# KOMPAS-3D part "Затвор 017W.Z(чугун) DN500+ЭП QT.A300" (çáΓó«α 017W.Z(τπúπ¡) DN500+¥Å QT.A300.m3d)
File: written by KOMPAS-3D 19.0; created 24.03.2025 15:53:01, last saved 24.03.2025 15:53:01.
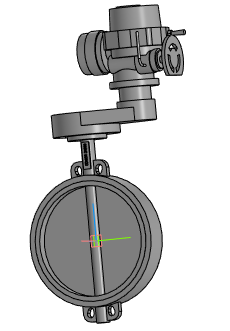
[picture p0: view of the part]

Document properties: Полное имя файла: Затвор 017W.Z(чугун) DN500+ЭП QT.A300.a3d

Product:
- Part/product: Затвор 017W.Z(чугун) DN500+ЭП QT.A300
    Масса: 362.481

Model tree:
1. Операция без истории:1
